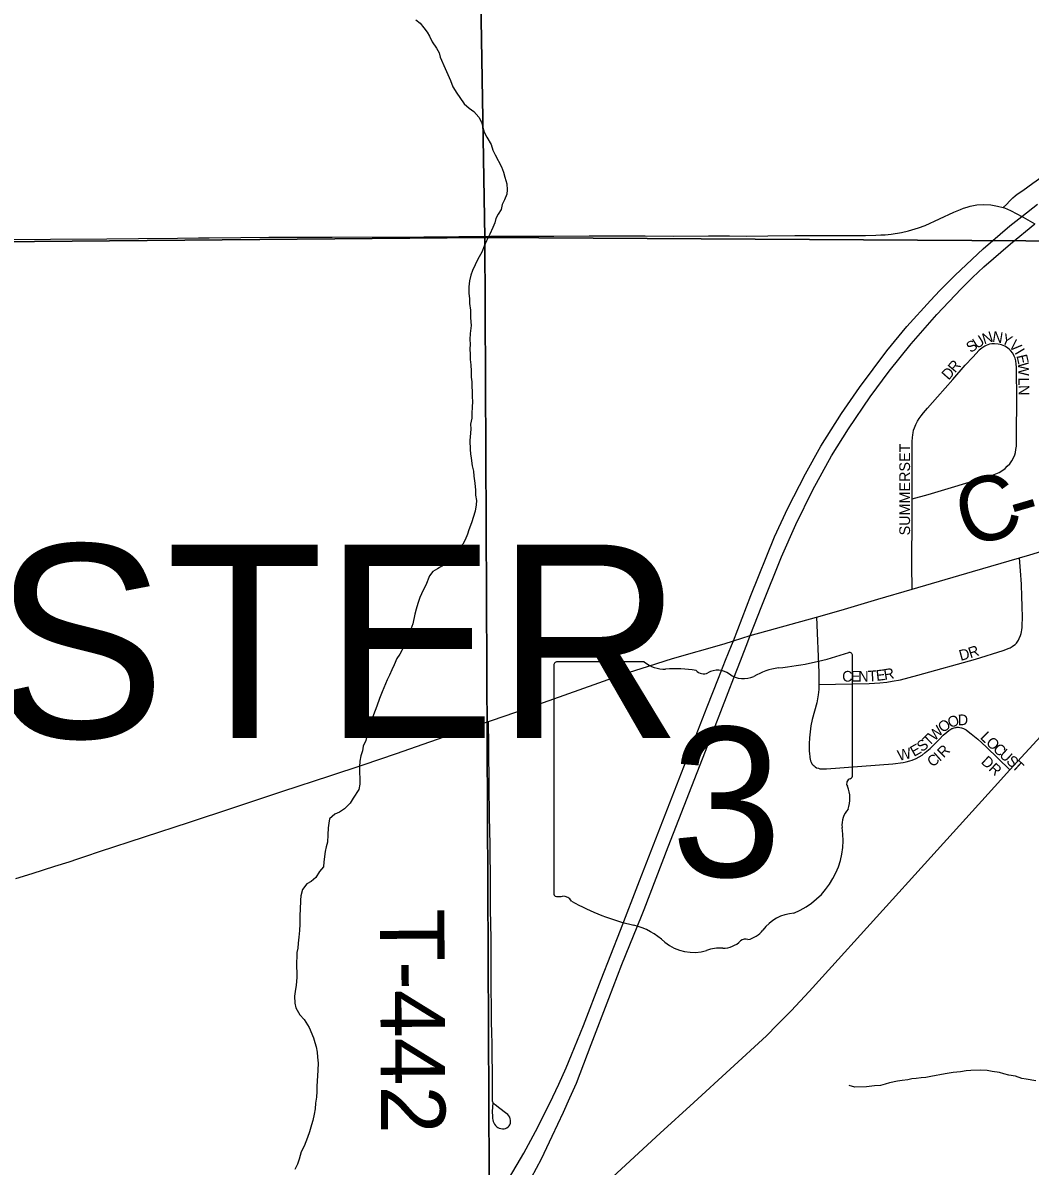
# Model space of a CAD drawing. Extents: x 1985906 to 2360102, y 891258 to 1222054.
# Drawn here: x 2112346 to 2117038, y 1010455 to 1015780 of the extents above; entities that cross this region are included whole.
import ezdxf

# ---------------------------------------------------------------- set-up
doc = ezdxf.new("R2010")
doc.units = 0
for name, color, linetype in [('GM_X_County_Road', 7, 'Continuous'), ('GM_X_County_Road_Text', 7, 'Continuous'), ('GM_X_Minor_River', 7, 'Continuous'), ('GM_X_Section', 7, 'Continuous'), ('GM_X_State_Location', 7, 'Continuous'), ('GM_X_State_Route', 7, 'Continuous'), ('GM_X_State_Shield', 7, 'Continuous'), ('GM_X_Township_Road', 7, 'Continuous'), ('GM_X_Township_Road_Text', 7, 'Continuous'), ('GM_X_Township_Subdivision', 7, 'Continuous'), ('GM_X_Township_Subdivision_Text', 7, 'Continuous'), ('GM_X_Township_Text', 7, 'Continuous')]:
    doc.layers.add(name, color=color, linetype=linetype)

msp = doc.modelspace()

# ---------------------------------------------------------------- linework, layer by layer
at = {"layer": 'GM_X_County_Road'}
for points in [[(2116216.8, 1014789.6), (2116271.3, 1014790.1), (2116319.9, 1014790.5), (2116343.3, 1014791.8), (2116363.9, 1014793), (2116390.5, 1014795.5), (2116439.3, 1014803.7), (2116471.5, 1014811), (2116518.7, 1014824.7), (2116549.2, 1014836.6), (2116683.2, 1014898.4), (2116714.5, 1014911.2), (2116728.7, 1014916.2), (2116744.7, 1014921.8), (2116759.2, 1014926.1), (2116790.9, 1014931.6), (2116823.1, 1014933.3), (2116855.3, 1014931.6), (2116887.2, 1014926.4), (2116913.2, 1014919.5)], [(2116913.2, 1014919.5), (2116918.3, 1014918.1), (2116933.3, 1014912.4), (2116947.7, 1014905.5), (2116976.2, 1014890.1), (2116999.5, 1014877.5)], [(2116999.5, 1014877.5), (2117005.3, 1014874.4), (2117060.2, 1014843.4)], [(2112280.3, 1014770.6), (2112475.9, 1014773), (2112738.2, 1014774), (2112885.9, 1014775.4), (2113066.5, 1014777.4), (2113164.9, 1014778.4), (2113214.1, 1014778.4), (2113361.6, 1014779.8), (2113492.8, 1014781.6), (2113656.6, 1014781.9), (2113787.5, 1014781.8), (2114213.7, 1014783.7), (2114377.5, 1014784.7), (2114459.4, 1014785.4), (2114525, 1014785.8), (2114607, 1014786.1), (2114819.9, 1014786.7), (2114983.7, 1014788.1), (2115147.6, 1014787.5), (2115172.5, 1014787.4)], [(2115172.5, 1014787.4), (2115245.7, 1014787.2), (2115376.2, 1014787), (2115539.7, 1014787.5), (2115637.8, 1014787.4), (2115719.4, 1014786.9), (2115817.3, 1014787.5), (2115942.6, 1014789)], [(2115942.6, 1014789), (2115947.4, 1014789), (2116127.7, 1014788.8), (2116216.8, 1014789.6)], [(2116988.5, 1013288.5), (2117037.7, 1013303), (2117128.1, 1013330), (2117189.4, 1013347.8), (2117282.9, 1013375.1), (2117506.2, 1013439.7), (2117566.8, 1013457.2), (2117607.2, 1013471.4), (2117668.3, 1013493.6), (2117734.3, 1013519.3), (2117917.7, 1013592.3), (2118085, 1013660.2), (2118128.2, 1013676.2), (2118152.3, 1013683.9), (2118167, 1013687.6), (2118194.9, 1013693.5)], [(2116489.7, 1013142.7), (2116770.2, 1013224.4), (2116988.5, 1013288.5)], [(2116043.5, 1013011.6), (2116158.2, 1013045.2), (2116236.6, 1013067.9), (2116329.3, 1013095.9), (2116489.7, 1013142.7)], [(2115734, 1012926), (2116043.5, 1013011.6)], [(2116943.9, 1012300.3), (2117104.9, 1012476.8), (2117153, 1012529)], [(2114543.7, 1009898.7), (2114582.7, 1009937.4), (2115013.2, 1010331.1), (2115315.3, 1010608.1), (2115472.7, 1010751.8), (2115809.7, 1011062.8), (2115859.7, 1011112.8), (2115925.8, 1011178.1), (2116009.8, 1011269), (2116069.3, 1011335.5), (2116575.6, 1011894.5), (2116873, 1012222.5), (2116943.9, 1012300.3)]]:
    msp.add_lwpolyline(points, dxfattribs=at)
at = {"layer": 'GM_X_Minor_River'}
for points in [[(2114176.9, 1015794.5), (2114197.2, 1015778.7), (2114213.5, 1015756.9), (2114229.9, 1015737), (2114240.2, 1015717.1), (2114252.6, 1015691.2), (2114273, 1015661.4), (2114285.3, 1015639.5), (2114289.6, 1015619.5), (2114314.4, 1015567.7), (2114339.2, 1015511.8), (2114349.7, 1015481.9), (2114368.1, 1015452.1), (2114382.4, 1015432.2), (2114402.9, 1015402.4), (2114425.2, 1015382.6), (2114447.5, 1015366.9), (2114470, 1015341.1), (2114482.3, 1015317.2)], [(2114482.3, 1015317.2), (2114488.6, 1015293.2), (2114495, 1015271.2), (2114507.3, 1015247.3), (2114527.8, 1015213.5), (2114536.2, 1015187.5), (2114546.5, 1015165.6), (2114575.4, 1015109.9), (2114585.8, 1015083.9), (2114592.1, 1015061.9), (2114600.5, 1015030), (2114602.9, 1015001.9), (2114601.1, 1014981.8), (2114589.4, 1014955.6), (2114579.7, 1014933.4), (2114573.9, 1014911.3), (2114560.2, 1014889), (2114550.4, 1014868.8), (2114544.6, 1014848.7), (2114534.9, 1014826.5), (2114521.2, 1014796.2), (2114505.6, 1014763.9), (2114495.8, 1014739.8), (2114484.2, 1014711.5), (2114466.5, 1014679.2), (2114441.1, 1014626.7), (2114433.3, 1014604.5), (2114427.7, 1014578.4), (2114424, 1014550.3), (2114424.4, 1014520.2), (2114426.7, 1014494.1), (2114427, 1014472.1), (2114431.4, 1014442), (2114431.9, 1014406), (2114434.4, 1014369.9), (2114430.8, 1014333.7), (2114429.2, 1014305.6), (2114429.5, 1014283.6), (2114427.8, 1014259.5), (2114430.1, 1014237.5), (2114430.4, 1014211.4), (2114432.7, 1014187.3), (2114435.1, 1014157.3), (2114435.5, 1014129.2), (2114437.8, 1014107.2), (2114438.7, 1014041), (2114441, 1014013), (2114439.3, 1013992.9), (2114437.7, 1013958.8), (2114438, 1013938.7), (2114432.3, 1013910.6), (2114432.6, 1013888.5), (2114430.9, 1013868.4), (2114429.3, 1013834.3), (2114429.8, 1013792.2), (2114432.1, 1013772.2), (2114434.4, 1013752.1), (2114438.9, 1013716.1), (2114445.2, 1013692.1), (2114447.5, 1013668.1), (2114452, 1013636), (2114454.4, 1013604), (2114454.7, 1013579.9), (2114459, 1013555.9), (2114457.3, 1013535.8), (2114453.6, 1013505.7), (2114436.3, 1013451.3), (2114424.6, 1013419.1), (2114416.9, 1013398.9), (2114407.2, 1013372.7), (2114395.4, 1013352.5), (2114369.7, 1013324.1), (2114343.8, 1013305.7), (2114320, 1013279.3), (2114298.3, 1013248.9), (2114278.4, 1013236.6), (2114256.5, 1013224.3), (2114240.7, 1013204), (2114223.2, 1013161.7), (2114211.4, 1013137.4), (2114195.8, 1013103.1), (2114186.1, 1013074.9), (2114178.4, 1013048.7), (2114172.7, 1013026.6), (2114163.3, 1012980.3), (2114153.6, 1012956.2), (2114147.8, 1012934), (2114140.1, 1012909.8), (2114126.4, 1012883.6), (2114102.9, 1012839.1), (2114089.1, 1012818.9), (2114075.4, 1012790.6), (2114065.6, 1012766.4), (2114053.9, 1012742.2), (2114044.2, 1012720), (2114020.8, 1012663.5), (2114007.1, 1012633.3), (2113995.6, 1012597), (2113980, 1012556.7), (2113972.3, 1012534.5), (2113964.6, 1012506.4)], [(2113964.6, 1012506.4), (2113949.2, 1012458), (2113943.4, 1012437.9), (2113931.7, 1012411.7), (2113928, 1012389.5), (2113920.3, 1012365.4), (2113916.5, 1012341.2), (2113914.9, 1012315.2), (2113915.9, 1012234.9), (2113912.2, 1012208.8), (2113884.7, 1012168.3), (2113870.9, 1012146.1), (2113845.1, 1012119.7), (2113821.2, 1012103.3), (2113799.3, 1012095), (2113775.5, 1012072.6), (2113771.7, 1012052.5), (2113768, 1012030.4), (2113766.4, 1011998.3), (2113764.8, 1011964.2), (2113759.1, 1011942), (2113755.4, 1011919.9), (2113747.9, 1011871.7), (2113746.2, 1011849.6), (2113728.4, 1011827.3), (2113710.7, 1011799), (2113688.9, 1011780.6), (2113668.9, 1011770.3), (2113649.2, 1011744), (2113641.6, 1011713.8), (2113639.8, 1011693.7), (2113638.4, 1011649.6), (2113636.7, 1011625.5), (2113637.3, 1011581.4), (2113635.6, 1011553.3), (2113632, 1011521.1), (2113628.4, 1011493), (2113626.7, 1011470.9), (2113622.9, 1011450.8), (2113623.2, 1011428.8), (2113621.5, 1011406.7), (2113622.4, 1011334.5), (2113618.9, 1011298.3), (2113615.2, 1011268.2), (2113611.5, 1011246.1), (2113613.9, 1011214), (2113618.2, 1011192), (2113636.7, 1011160.2), (2113657.1, 1011138.4), (2113679.7, 1011100.6), (2113700.4, 1011052.7), (2113706.7, 1011030.8), (2113713, 1011010.8), (2113717.3, 1010986.8), (2113719.6, 1010962.7), (2113722, 1010934.7), (2113720.4, 1010902.6), (2113718.7, 1010876.5), (2113715.3, 1010828.3), (2113715.7, 1010802.2), (2113714, 1010776.1), (2113710.3, 1010748), (2113708.7, 1010721.9), (2113703, 1010697.8), (2113697.3, 1010667.6), (2113691.6, 1010647.5), (2113682, 1010615.2), (2113672.3, 1010589), (2113656.7, 1010548.7), (2113643, 1010522.5), (2113633.4, 1010488.2), (2113625.7, 1010464.1), (2113614, 1010439.8)], [(2116740.6, 1010898.8), (2116714.6, 1010894.4), (2116680.5, 1010891.9), (2116642.4, 1010885.4), (2116576.3, 1010872.5), (2116552.2, 1010868.2), (2116530.2, 1010865.9), (2116508.1, 1010863.6), (2116488.1, 1010861.3), (2116468.1, 1010857), (2116442, 1010854.7), (2116419.9, 1010850.3), (2116383.9, 1010843.8), (2116363.9, 1010837.6), (2116341.9, 1010831.3), (2116313.8, 1010828.9), (2116275.7, 1010824.4), (2116221.5, 1010823.6), (2116195.3, 1010831.3)], [(2117064.5, 1010852.9), (2117020.2, 1010860.4), (2117000.1, 1010864.1), (2116969.9, 1010873.7), (2116939.7, 1010879.3), (2116915.5, 1010885), (2116895.3, 1010890.8), (2116861.1, 1010896.3), (2116839, 1010900.1), (2116808.8, 1010901.7), (2116762.7, 1010901), (2116740.6, 1010898.8)]]:
    msp.add_lwpolyline(points, dxfattribs=at)
at = {"layer": 'GM_X_Section'}
for points in [[(2108533.3, 1020120), (2114408.8, 1020130.7), (2114498.3, 1014780.1), (2108555.1, 1014727), (2108553.5, 1014965.1)], [(2119792.3, 1020106.2), (2119789.7, 1014747.1), (2114498.3, 1014780.1), (2114408.8, 1020130.7)], [(2108555.1, 1014727), (2114498.3, 1014780.1), (2114523.8, 1009415.2), (2108532.4, 1009391.8), (2108531.5, 1009537.9)], [(2114498.3, 1014780.1), (2119789.7, 1014747.1), (2119862.8, 1009456.5), (2114523.8, 1009415.2)]]:
    msp.add_lwpolyline(points, close=True, dxfattribs=at)
at = {"layer": 'GM_X_State_Route'}
for points in [[(2114613.4, 1010401.7), (2114679.5, 1010515.3), (2114734.8, 1010616.3), (2114801.5, 1010748.3), (2114843.3, 1010837.6), (2114876.9, 1010912.7), (2114902.6, 1010973.1), (2114958.1, 1011110.1), (2115040.9, 1011324.6), (2115129.6, 1011554.3), (2115219.5, 1011783.5), (2115534, 1012594.7), (2115586.8, 1012727.5), (2115620.2, 1012811.4), (2115647.5, 1012880.2), (2115656.3, 1012902.1), (2115737.3, 1013113.1), (2115848.1, 1013385.4), (2115909.3, 1013519.4), (2115991.5, 1013679.7), (2116064, 1013807.9), (2116159.7, 1013960.4), (2116243.9, 1014081.3), (2116371, 1014252), (2116464.6, 1014365.7), (2116574.2, 1014487.1), (2116618.6, 1014533.3), (2116688.1, 1014602.8), (2116741.9, 1014654), (2116820.3, 1014726.8), (2116944, 1014833.8), (2116999.5, 1014877.5), (2117072.2, 1014935.3)], [(2115734, 1012926), (2115788.7, 1013064.1), (2115880.4, 1013292.7), (2115946.4, 1013443.2), (2116026.9, 1013605), (2116113.9, 1013763.5), (2116191.9, 1013889.2), (2116293.4, 1014038.7), (2116381.3, 1014157.6), (2116484.5, 1014285.3), (2116603.8, 1014421), (2116716.5, 1014540.5), (2116769.7, 1014593.2), (2116823, 1014642.9), (2116946.4, 1014751.3), (2117060.2, 1014843.4)], [(2112313.8, 1011794.3), (2112390.5, 1011818.7), (2112495.5, 1011851.6), (2112562.6, 1011872.6), (2112602.6, 1011886.3), (2112640.1, 1011899.2), (2112704.2, 1011920.2), (2113123.1, 1012057.7), (2113325.2, 1012124.6), (2113558, 1012202.2), (2113776.3, 1012273.2), (2113932, 1012324.6), (2114087.2, 1012377.6), (2114211, 1012420.8), (2114412.2, 1012490.6), (2114515.4, 1012525.8), (2114520.4, 1012527.5), (2114597.3, 1012553.3), (2114797.9, 1012624.1), (2115029.7, 1012705.7), (2115137.7, 1012744.6), (2115260.1, 1012783.3), (2115372.2, 1012818.8), (2115613.6, 1012887.8), (2115656.3, 1012902.1), (2115734, 1012926)], [(2114537.7, 1010104.9), (2114561.9, 1010144), (2114699.2, 1010370), (2114716.2, 1010402.2), (2114762.2, 1010489), (2114812.3, 1010594.2), (2114865.6, 1010706.1), (2114895.1, 1010773.8), (2114925, 1010842.2), (2114993.3, 1011021.3), (2115075.9, 1011235.7), (2115136.6, 1011394.6), (2115227.8, 1011619.5), (2115240.5, 1011650.9), (2115352.5, 1011942.7), (2115537, 1012416.4), (2115632.1, 1012660.9), (2115658.3, 1012729.2), (2115688.7, 1012808.2), (2115723.1, 1012897.5), (2115734, 1012926)]]:
    msp.add_lwpolyline(points, dxfattribs=at)
at = {"layer": 'GM_X_State_Shield'}
for p, q in [((2116211.3, 1012277), (2116211.3, 1012829.7)), ((2114819.2, 1012785.3), (2114819.2, 1011728.7)), ((2115240.6, 1012803.5), (2114832.9, 1012803.5)), ((2116211.2, 1012277.1), (2116211.3, 1012277))]:
    msp.add_line(p, q, dxfattribs=at)
for centre, radius, start, end in [((2115715.4, 1014244.1), 1476.4, 275.8445, 288.9065), ((2116195.9, 1012832), 15.5, 351.8621, 97.738), ((2114835.1, 1012787.6), 16.1, 98.1301, 188.1301), ((2115337.7, 1012926.2), 156.4, 231.6195, 271.1119), ((2115903.7, 1012480.8), 297, 97.3462, 120.7689), ((2115389.5, 1012210.3), 561.6, 80.4867, 94.9883), ((2115517, 1012793.1), 45.1, 219.7921, 297.1024), ((2115583.3, 1012670.9), 93.8, 54.4667, 119.1411), ((2115704.4, 1012838.5), 112.9, 233.8562, 294.8282), ((2116207.7, 1012236.4), 24, 107.944, 210.337), ((2116194.8, 1012274.8), 16.6, 289.6038, 7.7341), ((2116055.1, 1012166.5), 144, 340.033, 23.6496), ((2116266.8, 1012045.7), 104.8, 136.8065, 186.9296), ((2115798.1, 1011975.3), 369.3, 292.3089, 8.9858), ((2114835.2, 1011726.4), 16.3, 171.9584, 258.3066), ((2114837.7, 1011834.5), 124.2, 267.339, 280.6039), ((2114863.1, 1011667.7), 44.8, 29.7484, 93.2717), ((2115428.4, 1012617.1), 1066.1, 240.4129, 257.1985), ((2115953.8, 1011432.1), 202.2, 94.4031, 142.5768), ((2115110.5, 1011254), 333.6, 47.1842, 75.836), ((2115697.6, 1011626.3), 119.3, 282.8732, 323.2771), ((2115471.3, 1011662.5), 211.7, 230.7004, 286.2918), ((2115609.1, 1011583.4), 112.8, 268.777, 315.5493), ((2115711.1, 1011481), 31.8, 65.7517, 132.6484), ((2115593.6, 1011297.2), 173.9, 85.6951, 111.2099)]:
    msp.add_arc(centre, radius, start, end, dxfattribs=at)
at = {"layer": 'GM_X_Township_Road'}
msp.add_lwpolyline([(2114535.2, 1010750), (2114533.2, 1010709.2), (2114533.5, 1010685.7), (2114534.4, 1010677.2), (2114535.9, 1010670.2), (2114537.9, 1010663.7), (2114540.9, 1010656.2), (2114544.2, 1010650.5), (2114548.7, 1010643.8), (2114553.9, 1010638.7), (2114559.6, 1010635.1), (2114565, 1010632.6), (2114572.2, 1010630.6), (2114580, 1010629.5), (2114587.9, 1010629.1), (2114594.8, 1010630.6), (2114600.9, 1010633.6), (2114607.3, 1010638), (2114611.9, 1010643.2), (2114615.2, 1010648.3), (2114617.4, 1010654.6), (2114618.1, 1010661.8), (2114617.8, 1010669.2), (2114616.5, 1010676.3), (2114614.1, 1010683.5), (2114610.3, 1010689.3), (2114604.9, 1010695.3), (2114594.4, 1010703.9), (2114567.7, 1010723.4), (2114546.4, 1010740), (2114541.2, 1010745), (2114537.5, 1010749.3), (2114535.6, 1010753.4), (2114534.5, 1010757.3), (2114533.8, 1010761.1), (2114534, 1010787), (2114534.3, 1010835.6), (2114534.1, 1010892), (2114532.6, 1010970.2), (2114531.8, 1011028.4), (2114531, 1011074.4), (2114530.1, 1011128.2), (2114529.1, 1011210.7), (2114528.4, 1011264.5), (2114527.8, 1011317.5), (2114528, 1011354), (2114528.6, 1011440), (2114527.3, 1011516), (2114524.9, 1011650.5), (2114524.5, 1011683.3), (2114524.5, 1011823.7), (2114523.6, 1011894.1), (2114522.8, 1011953.7), (2114520.3, 1012082.7), (2114518.6, 1012231), (2114517.9, 1012290.9), (2114517.4, 1012340.4), (2114516.9, 1012384.7), (2114516.4, 1012431.6), (2114515.6, 1012507.9), (2114515.4, 1012525.8)], dxfattribs=at)
at = {"layer": 'GM_X_Township_Subdivision'}
for points in [[(2117003.7, 1014999.8), (2117051, 1015033.6), (2117172, 1015118.1), (2117239.5, 1015163.8), (2117335.8, 1015225), (2117488.6, 1015319.4), (2117766.1, 1015491.4), (2117861.9, 1015553.7), (2117968.5, 1015628.6), (2118047.7, 1015685.8), (2118073.6, 1015705.3)], [(2116913.2, 1014919.5), (2116927.8, 1014934.6), (2116943.4, 1014951.1), (2116957.9, 1014964.4), (2116968.4, 1014973.9), (2116978.1, 1014981.5), (2117003.7, 1014999.8)], [(2116488.4, 1013563.2), (2116563.9, 1013584), (2116847, 1013668), (2116862.8, 1013673.3), (2116879, 1013679.4), (2116893.9, 1013686.4), (2116907, 1013693.8), (2116921.4, 1013705), (2116932.2, 1013714.9), (2116943.4, 1013726.8), (2116953.1, 1013740), (2116961, 1013754.4), (2116967.2, 1013768.3), (2116970.1, 1013779.4), (2116972.6, 1013793.5), (2116974.5, 1013808.9), (2116975.3, 1013823.1), (2116975.2, 1013844), (2116976, 1014047.8), (2116975.4, 1014146.2), (2116974.7, 1014176.6), (2116973.7, 1014190.7), (2116971.6, 1014205.4), (2116968.5, 1014218), (2116964.8, 1014226.9), (2116957.1, 1014241.4), (2116947.1, 1014254.4), (2116940.8, 1014260.4), (2116935, 1014265.4), (2116927.9, 1014269.7), (2116921, 1014273.9), (2116913.2, 1014277.5), (2116905.7, 1014280), (2116898.1, 1014282.3), (2116889.8, 1014283.9), (2116871.9, 1014285.1), (2116865.5, 1014285.5), (2116859.6, 1014284.8), (2116849.9, 1014283), (2116841.8, 1014280.6), (2116833.8, 1014277.5), (2116826.8, 1014274), (2116813.1, 1014265.1), (2116801.8, 1014255.5)], [(2116488.4, 1013563.2), (2116488.5, 1013796.5), (2116489, 1013830.2), (2116489.9, 1013848.6), (2116491.3, 1013860.7), (2116493.4, 1013870.9), (2116495.9, 1013882.2), (2116499.9, 1013894.2), (2116506.1, 1013909.8), (2116513.3, 1013924.3), (2116521.4, 1013937), (2116530.5, 1013949.4), (2116542.5, 1013964.2), (2116560, 1013984.7), (2116607.3, 1014038.5), (2116678.6, 1014119.4), (2116736.1, 1014185), (2116772, 1014223.5), (2116801.8, 1014255.5)], [(2116489.7, 1013142.7), (2116488, 1013253.3), (2116488.4, 1013484), (2116488.4, 1013563.2)], [(2116054.8, 1012698.8), (2116288.6, 1012703.7), (2116337.6, 1012706), (2116370.4, 1012709.5), (2116396.5, 1012713.3), (2116435.1, 1012720.7), (2116514.6, 1012741.3), (2116783.6, 1012817), (2116912.3, 1012856.4), (2116925.4, 1012861.2), (2116935.8, 1012865.3), (2116944.9, 1012869.7), (2116954.3, 1012874.8), (2116961.5, 1012880), (2116968.1, 1012885.4), (2116974.9, 1012891.5), (2116981, 1012899.8), (2116984.4, 1012905.1), (2116987.9, 1012912), (2116993.3, 1012926.4), (2116996.4, 1012935.9), (2116998.2, 1012943.3), (2117000.3, 1012953.6), (2117001.6, 1012964.4), (2117001.8, 1012974.7), (2117002.5, 1013008.4), (2117001.5, 1013064.9), (2117000.4, 1013107.3), (2116997.8, 1013166.4), (2116993.3, 1013227.7), (2116988.5, 1013288.5)], [(2116043.5, 1013011.6), (2116053.8, 1012754.7), (2116054.8, 1012698.8)], [(2116054.8, 1012698.8), (2116054.8, 1012689), (2116054.4, 1012675.2), (2116052.9, 1012662.6), (2116051.1, 1012650.7), (2116044.2, 1012613.7), (2116022.6, 1012535), (2116016.9, 1012505.8), (2116013.7, 1012478.2), (2116011, 1012449.2), (2116009.3, 1012422.7), (2116009.4, 1012391.2), (2116010.4, 1012374.3), (2116011.7, 1012364.8), (2116012.5, 1012358.5), (2116013.9, 1012351), (2116015.9, 1012343.4), (2116018.3, 1012336.8), (2116022.2, 1012329.6), (2116027.8, 1012322.9), (2116031.9, 1012318.9), (2116036.6, 1012314.9), (2116044, 1012310.4), (2116051.9, 1012308), (2116058.6, 1012306.3), (2116066.3, 1012305.2), (2116078.5, 1012305.2), (2116090.2, 1012304.9), (2116399.1, 1012328.7), (2116447.2, 1012335.2), (2116461.5, 1012338.1), (2116478.3, 1012342.7), (2116489.7, 1012346.7), (2116508.2, 1012354.2), (2116522.2, 1012361.5), (2116535.8, 1012370), (2116549.5, 1012380.9), (2116573.1, 1012400.4), (2116615.6, 1012443.4), (2116634.1, 1012462), (2116650.5, 1012476.5), (2116659.9, 1012483.7), (2116669, 1012490.2), (2116673.7, 1012492.7), (2116676.5, 1012494.2), (2116680, 1012495.5), (2116685, 1012497), (2116690.2, 1012498.1), (2116694, 1012498.6), (2116697.7, 1012499)], [(2116697.7, 1012499), (2116702, 1012499), (2116705.1, 1012499), (2116711.2, 1012498.4), (2116718.3, 1012497), (2116723.1, 1012495.7), (2116728.2, 1012493.9), (2116734.2, 1012491), (2116740.9, 1012486.8), (2116750.4, 1012480.2), (2116763.7, 1012469.2), (2116794.4, 1012443.2), (2116833.3, 1012407.5), (2116943.9, 1012300.3)]]:
    msp.add_lwpolyline(points, dxfattribs=at)

# ---------------------------------------------------------------- texts
at = {"layer": 'GM_X_County_Road_Text'}
for s, rotation, p in [('C', 16.304, (2116742.3, 1013333.2)), ('-', 16.3039, (2116977.1, 1013401.8))]:
    msp.add_text(s, height=300, rotation=rotation, dxfattribs=at).set_placement(p)
at = {"layer": 'GM_X_State_Location'}
for s in ['s', 'r']:
    msp.add_text(s, height=1, dxfattribs=at).set_placement((2115499.5, 1012186.8))
msp.add_text('3', height=1, rotation=0, dxfattribs=at).set_placement((2115348.9, 1012114))
at = {"layer": 'GM_X_State_Shield'}
msp.add_text('3', height=696.1, dxfattribs=at).set_placement((2115365.1, 1011803.2))
at = {"layer": 'GM_X_Township_Road_Text'}
msp.add_text('T-442', height=300, rotation=270.2824, dxfattribs=at).set_placement((2114009.8, 1011654.5))
at = {"layer": 'GM_X_Township_Subdivision_Text'}
for s, rotation, p in [('U', 32.4896, (2116790.3, 1014260.1)), ('N', 17.8958, (2116824.3, 1014282.3)), ('N', 351.0012, (2116860.1, 1014295.4)), ('Y', 335.9721, (2116900.2, 1014289.5)), ('S', 32.5079, (2116760.6, 1014241.2)), ('V', 312.9132, (2116936.1, 1014274.6)), ('I', 300.87, (2116964.4, 1014244.6)), ('E', 283.0786, (2116974.2, 1014229.5)), ('D', 48.2703, (2116658.4, 1014112.9)), ('R', 50.055, (2116688.8, 1014147)), ('W', 271.4882, (2116981.8, 1014197.9)), ('L', 271.0791, (2116983.5, 1014127.6)), ('N', 271.0858, (2116984.2, 1014092.4)), ('SUMMERSET', 90, (2116479.1, 1013392.9)), ('D', 15.3299, (2116715, 1012808)), ('R', 17.8101, (2116759.7, 1012820.3)), ('R', 9.8143, (2116361, 1012719.3)), ('C', 0.17, (2116163, 1012711.5)), ('E', 0.1639, (2116202.6, 1012711.6)), ('N', 0.1639, (2116237.8, 1012711.7)), ('T', 3.9493, (2116285.4, 1012712)), ('E', 6.8035, (2116323.2, 1012714.7)), ('W', 43.9597, (2116592.5, 1012432.3)), ('O', 37.5606, (2116632.6, 1012471)), ('O', 17.5848, (2116663.4, 1012495.7)), ('D', 0.9618, (2116701.6, 1012508.4)), ('T', 44.3813, (2116567.4, 1012407.7)), ('L', 315.2125, (2116803.2, 1012449.2)), ('W', 12.9637, (2116427.1, 1012342.1)), ('E', 29.3954, (2116497.4, 1012360.6)), ('S', 37.3023, (2116534.3, 1012382)), ('R', 44.2661, (2116635.1, 1012354)), ('O', 316.8557, (2116829.3, 1012423.3)), ('C', 317.784, (2116862.1, 1012392.6)), ('C', 38.089, (2116583.1, 1012311)), ('I', 41.7808, (2116617, 1012337.7)), ('DR', 317.1199, (2116806.6, 1012334.3)), ('U', 317.8136, (2116891.4, 1012365.9)), ('S', 317.8118, (2116924, 1012336.4)), ('T', 317.8118, (2116950.1, 1012312.8))]:
    msp.add_text(s, height=50, rotation=rotation, dxfattribs=at).set_placement(p)
at = {"layer": 'GM_X_Township_Text'}
msp.add_text('WOOSTER', height=900, rotation=0, dxfattribs=at).set_placement((2109201.3, 1012449.8))

doc.saveas('drawing.dxf')
